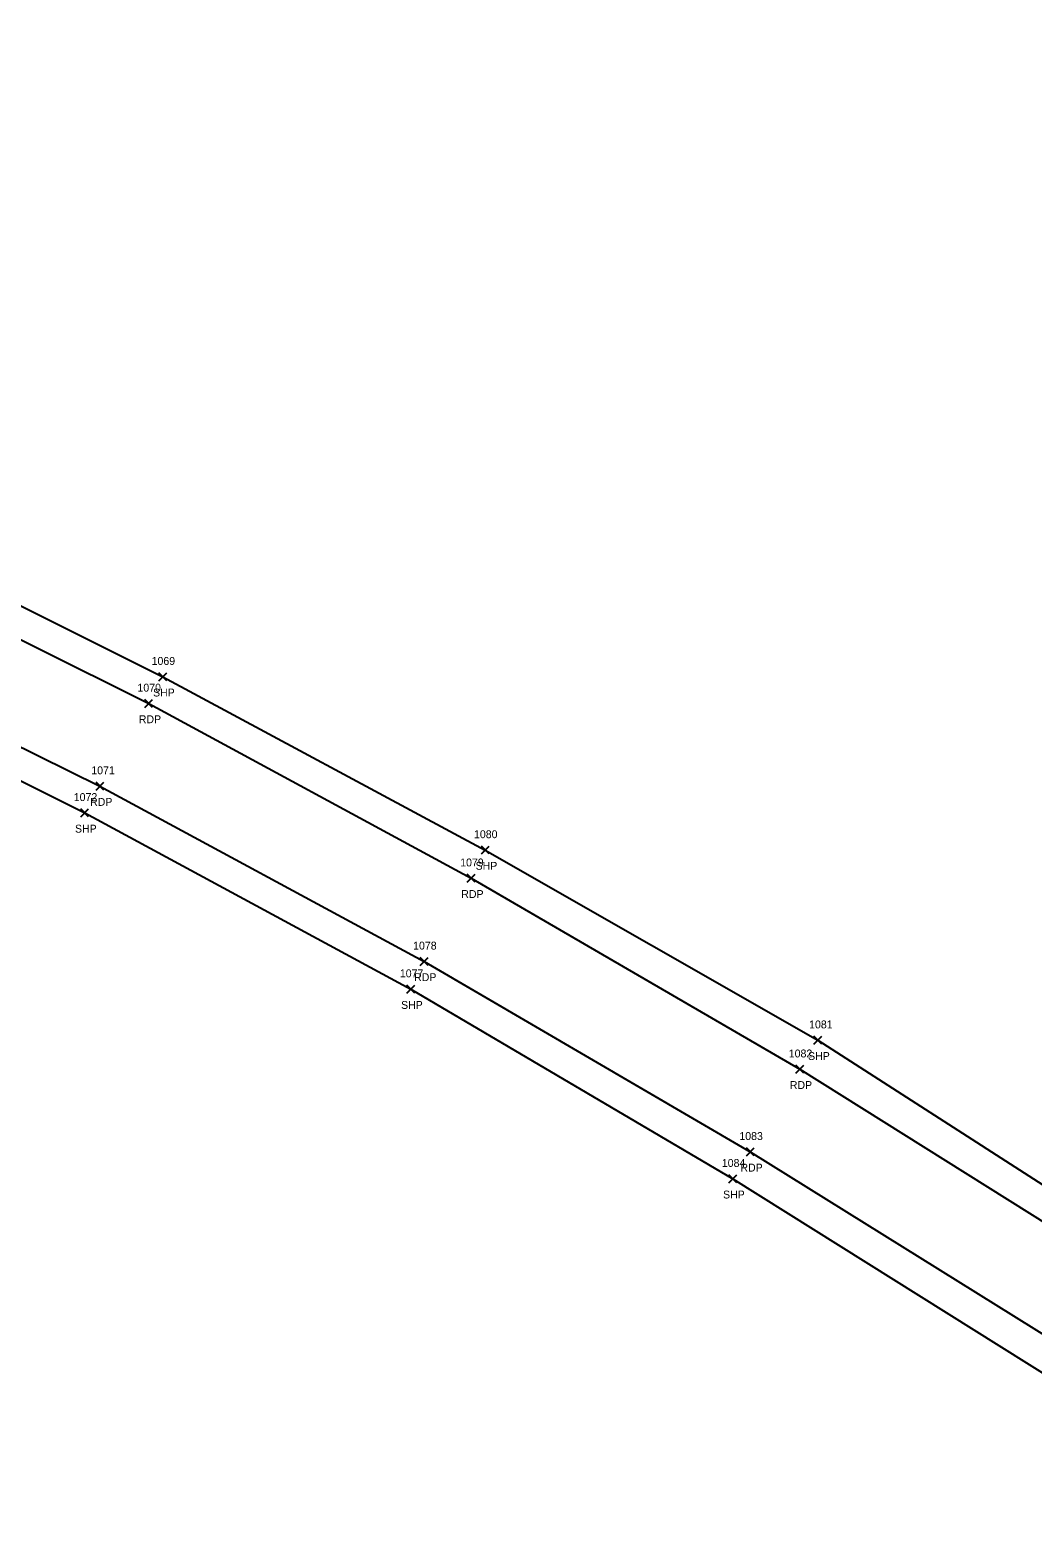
# Model space of a CAD drawing. Extents: x 1519347 to 1522636, y 378779 to 379832.
# Drawn here: x 1521873.5 to 1522127.4, y 379160.8 to 379542.8 of the extents above; entities that cross this region are included whole.
import ezdxf

# ---------------------------------------------------------------- set-up
doc = ezdxf.new("R2010")
doc.units = 0
for name, color, linetype in [('P_A', 7, 'Continuous'), ('P_I', 7, 'Continuous'), ('P_TIC', 7, 'Continuous'), ('PE', 7, 'Continuous'), ('PSP', 7, 'Continuous')]:
    doc.layers.add(name, color=color, linetype=linetype)

msp = doc.modelspace()

# ---------------------------------------------------------------- linework, layer by layer
at = {"layer": 'P_TIC'}
for points in [[(1521906.05, 379377.96), (1521908.05, 379379.96)], [(1521908.05, 379377.96), (1521906.05, 379379.96)], [(1521902.5, 379371.19), (1521904.5, 379373.19)], [(1521904.5, 379371.19), (1521902.5, 379373.19)], [(1521890.16, 379350.25), (1521892.16, 379352.25)], [(1521892.16, 379350.25), (1521890.16, 379352.25)], [(1521886.29, 379343.47), (1521888.29, 379345.47)], [(1521888.29, 379343.47), (1521886.29, 379345.47)], [(1521987.73, 379334.06), (1521989.73, 379336.06)], [(1521989.73, 379334.06), (1521987.73, 379336.06)], [(1521984.15, 379326.91), (1521986.15, 379328.91)], [(1521986.15, 379326.91), (1521984.15, 379328.91)], [(1521972.22, 379305.84), (1521974.22, 379307.84)], [(1521974.22, 379305.84), (1521972.22, 379307.84)], [(1521968.86, 379298.81), (1521970.86, 379300.81)], [(1521970.86, 379298.81), (1521968.86, 379300.81)], [(1522071.92, 379285.87), (1522073.92, 379287.87)], [(1522073.92, 379285.87), (1522071.92, 379287.87)], [(1522067.34, 379278.51), (1522069.34, 379280.51)], [(1522069.34, 379278.51), (1522067.34, 379280.51)], [(1522054.83, 379257.59), (1522056.83, 379259.59)], [(1522056.83, 379257.59), (1522054.83, 379259.59)], [(1522050.39, 379250.77), (1522052.39, 379252.77)], [(1522052.39, 379250.77), (1522050.39, 379252.77)]]:
    msp.add_lwpolyline(points, dxfattribs=at)
at = {"layer": 'PE'}
for points in [[(1521529.39, 379535.32), (1521632.62, 379496.8), (1521722.31, 379458.96), (1521816.06, 379415.75), (1521903.5, 379372.19), (1521985.15, 379327.91), (1522068.34, 379279.51), (1522152.8, 379226.58), (1522231.81, 379172.75), (1522311.43, 379114.1), (1522387.62, 379054.41), (1522460.96, 378992.6), (1522530.24, 378930.24), (1522627.42, 378835.6)], [(1521521.96, 379512.45), (1521622.97, 379474.43), (1521713.3, 379436.47), (1521805.17, 379393.75), (1521891.16, 379351.25), (1521973.22, 379306.84), (1522055.83, 379258.59), (1522137.28, 379207.8), (1522217.99, 379153.03), (1522296.46, 379094.97), (1522371.63, 379036.1), (1522445.19, 378974.11), (1522514.07, 378912.19), (1522609.78, 378819.15)]]:
    msp.add_lwpolyline(points, dxfattribs=at)
at = {"layer": 'PSP'}
for points in [[(1521531.82, 379542.79), (1521635.1, 379503.97), (1521725.46, 379466.08), (1521819.09, 379422.88), (1521907.05, 379378.96), (1521988.73, 379335.06), (1522072.92, 379286.87), (1522157.1, 379232.77), (1522235.26, 379178.41), (1522315.3, 379119.36), (1522391.65, 379059.53), (1522465.18, 378997.47), (1522534.68, 378934.98), (1522631.83, 378840.12)], [(1521519.02, 379505.15), (1521619.86, 379467.25), (1521710.1, 379429.27), (1521802.41, 379386.84), (1521887.29, 379344.47), (1521969.86, 379299.81), (1522051.39, 379251.77), (1522132.8, 379200.77), (1522213.2, 379146), (1522291.37, 379088.51), (1522366.45, 379029.85), (1522439.83, 378967.41), (1522509.25, 378905.3), (1522537.61, 378878.43), (1522603.87, 378813.19)]]:
    msp.add_lwpolyline(points, dxfattribs=at)

# ---------------------------------------------------------------- texts
at = {"layer": 'P_A'}
for s, p in [('SHP', (1521904.59, 379373.96)), ('RDP', (1521900.99, 379367.19)), ('RDP', (1521888.65, 379346.25)), ('SHP', (1521884.83, 379339.47)), ('SHP', (1521986.27, 379330.06)), ('RDP', (1521982.64, 379322.91)), ('RDP', (1521970.7, 379301.84)), ('SHP', (1521967.39, 379294.81)), ('SHP', (1522070.46, 379281.87)), ('RDP', (1522065.83, 379274.51)), ('RDP', (1522053.32, 379253.59)), ('SHP', (1522048.92, 379246.77))]:
    msp.add_text(s, height=2, dxfattribs=at).set_placement(p)
at = {"layer": 'P_I'}
for s, p in [('1069', (1521904.23, 379381.96)), ('1070', (1521900.65, 379375.19)), ('1071', (1521888.96, 379354.25)), ('1072', (1521884.52, 379347.47)), ('1080', (1521985.87, 379338.06)), ('1079', (1521982.37, 379330.91)), ('1078', (1521970.45, 379309.84)), ('1077', (1521967.09, 379302.81)), ('1081', (1522070.72, 379289.87)), ('1082', (1522065.57, 379282.51)), ('1083', (1522053.06, 379261.59)), ('1084', (1522048.62, 379254.77))]:
    msp.add_text(s, height=2, dxfattribs=at).set_placement(p)

doc.saveas('drawing.dxf')
